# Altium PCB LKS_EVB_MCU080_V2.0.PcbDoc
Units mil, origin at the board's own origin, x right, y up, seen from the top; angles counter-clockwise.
Board outline 2625 x 1560 mil, 2 copper layers (Top Layer, Bottom Layer); 45 components, 81 nets, 209 pads, 59 vias.
Unrouted connection lines stored in the file: 4.
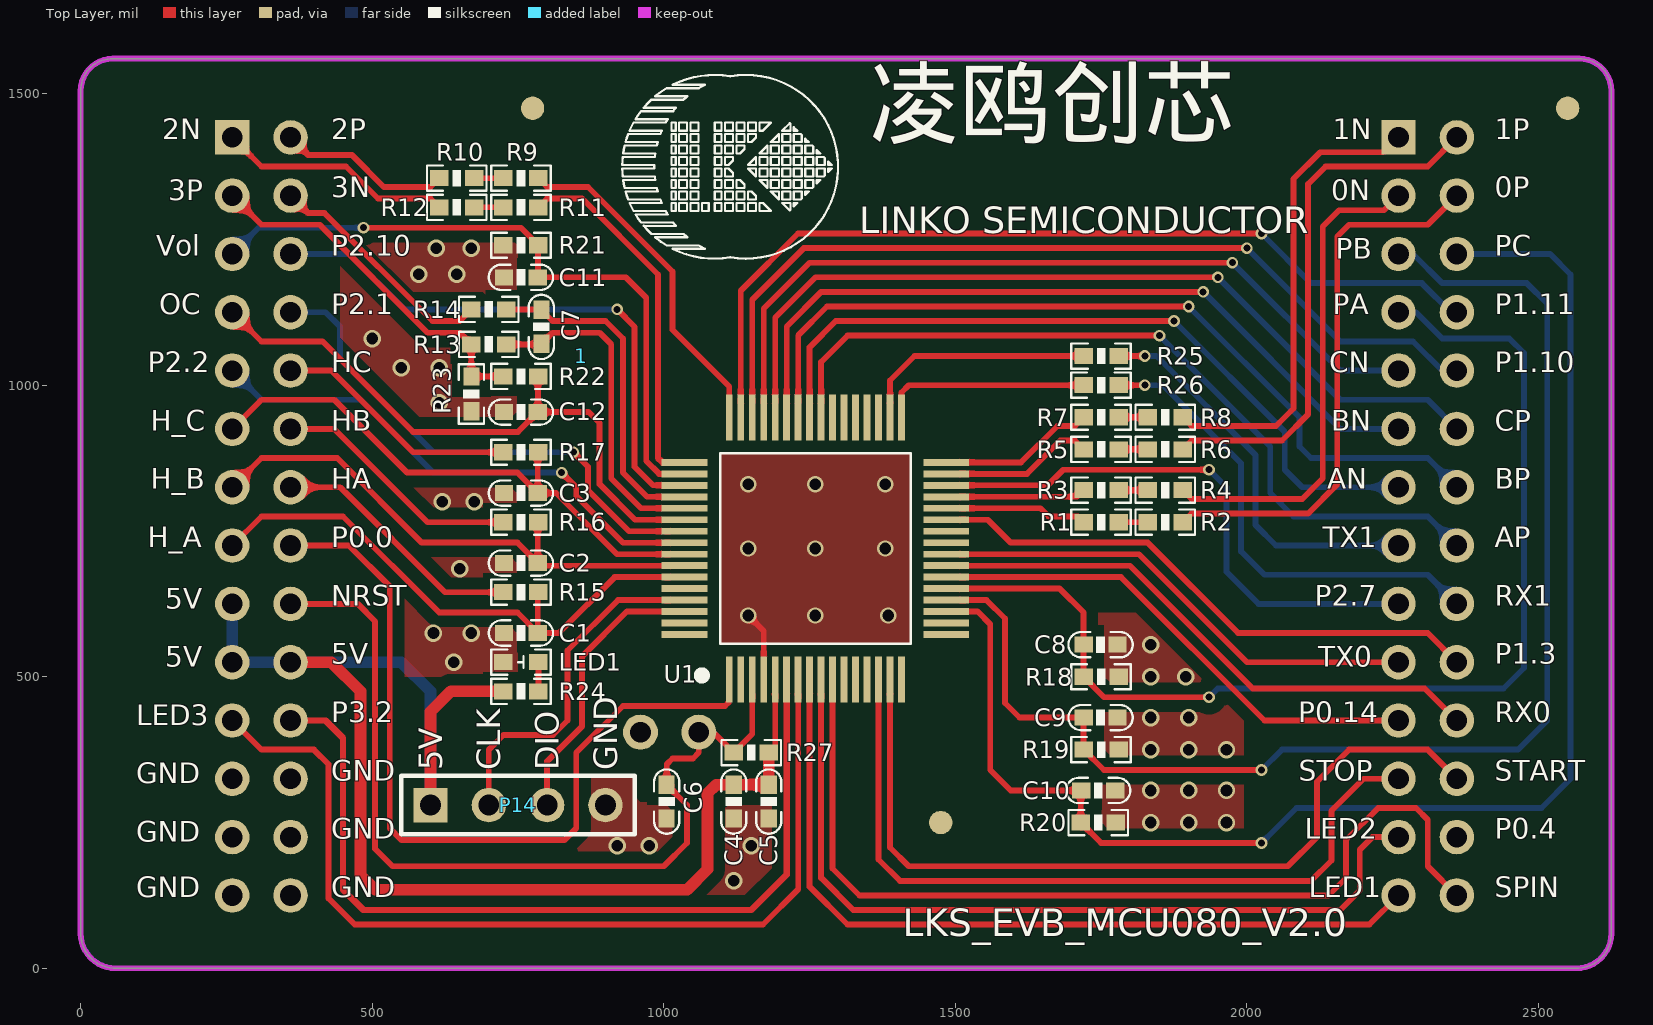
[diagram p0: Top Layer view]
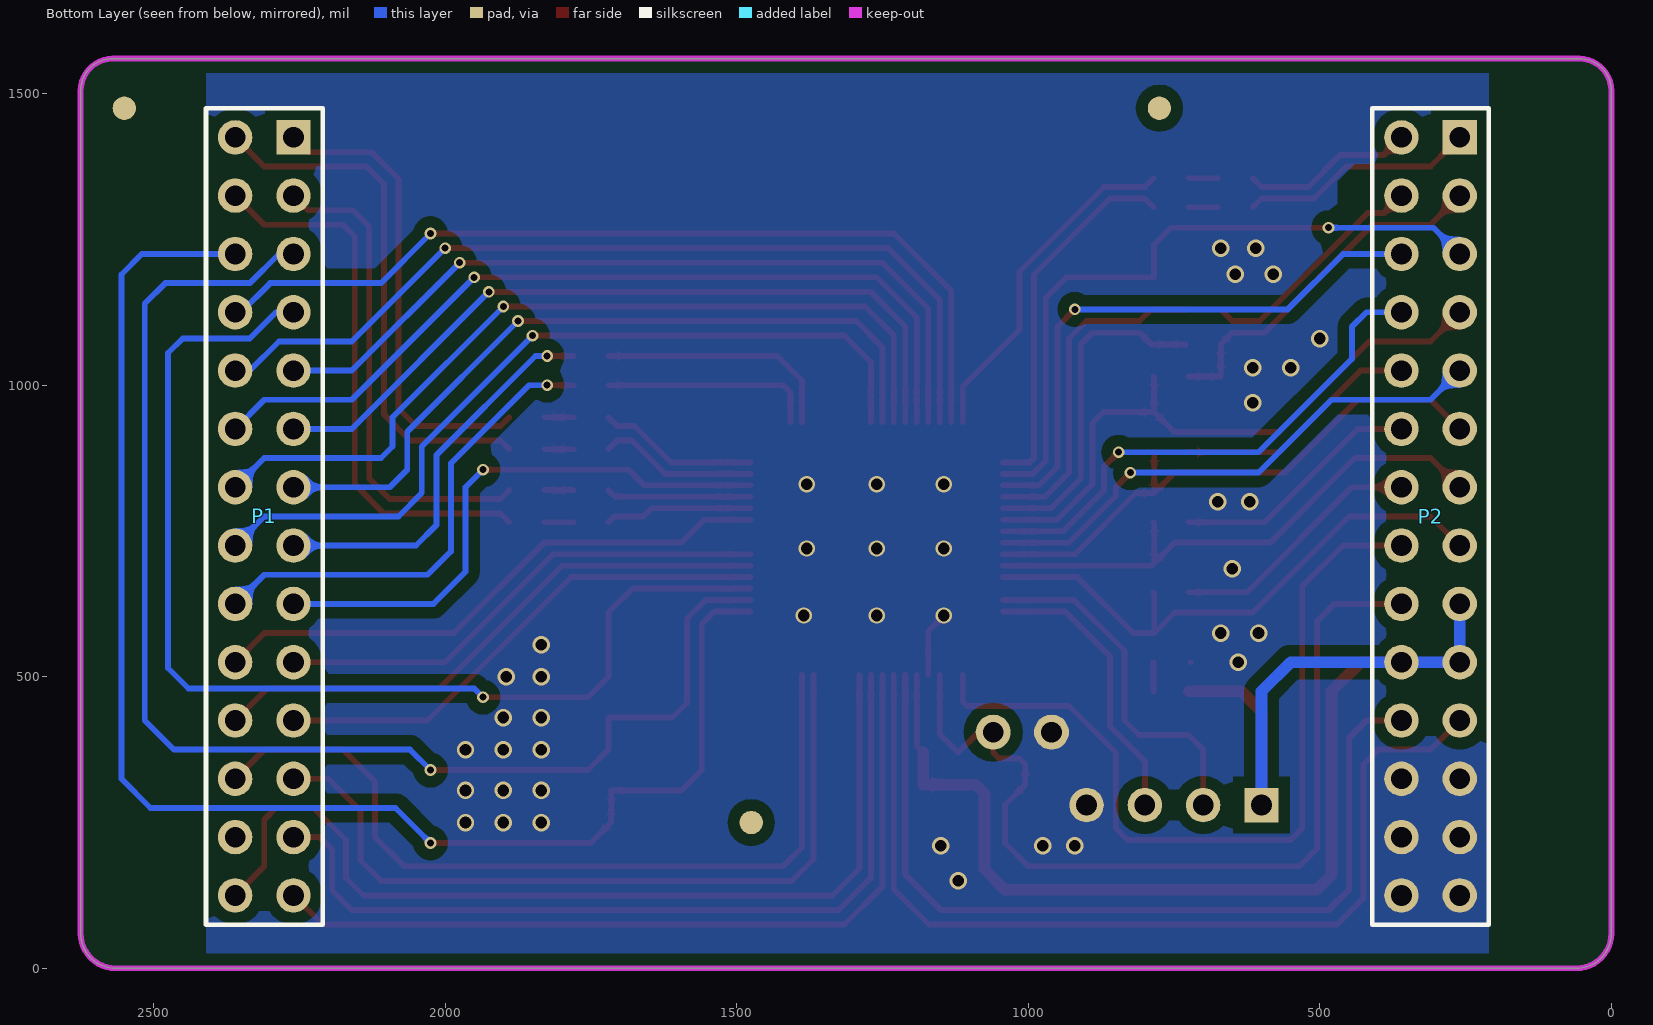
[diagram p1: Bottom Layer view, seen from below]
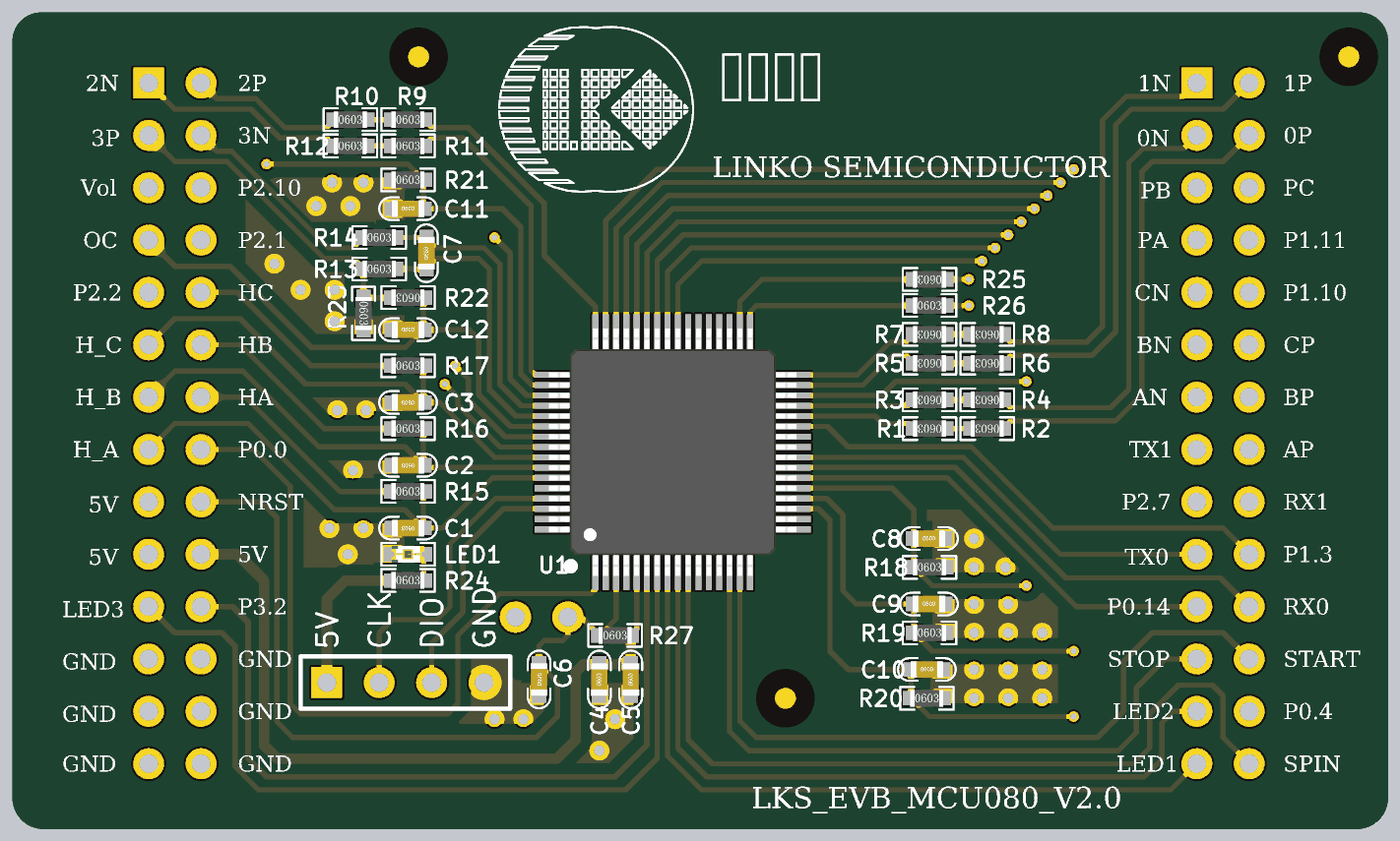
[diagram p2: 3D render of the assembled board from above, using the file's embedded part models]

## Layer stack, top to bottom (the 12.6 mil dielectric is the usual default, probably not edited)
Top Solder: solder mask 0.4, Solder Resist, Dk 3.5
Top Layer: signal copper 1.4
Dielectric1: dielectric 12.6, FR-4, Dk 4.8
Bottom Layer: signal copper 1.4
Bottom Solder: solder mask 0.4, Solder Resist, Dk 3.5

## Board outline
0,60 0,1505 cw(c55,1505) 55,1560 2570,1560 cw(c2570,1505) 2625,1505 2625,60 cw(c2565,60) 2565,0 60,0 cw(c60,60)

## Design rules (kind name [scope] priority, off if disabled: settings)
Clearance Clearance_2 [InPolygon] p1: gap=20 ignorepadtopadclearanceinfootprint=FALSE except(0: Arc-Hole Track-Hole SMDPad-Hole THPad-Hole Via-Hole Fill-Hole Poly-Hole Region-Hole Text-Hole)
Clearance Clearance_1 [All] p2: gap=0 ignorepadtopadclearanceinfootprint=FALSE
ComponentClearance [All] p1: gap=0 collisioncheckmode=3 verticalgap=0 showdistances=FALSE
FabricationTestpoint [(IsPad And (OnTopLayer Or OnBottomLayer))] p1: side=3 testpointundercomponent=TRUE minsize=40 maxsize=100 preferedsize=60 minholesize=0 maxholesize=40 preferedholesize=32 testpointgrid=1 allowsidetop=TRUE allowsidebottom=TRUE usegrid=TRUE gridtolerance=0.01
HoleSize [All] p1: absolutevalues=TRUE maxlimit=100 minlimit=0 maxpercent=80.000 minpercent=20.000
PolygonConnect [All] p1: connectstyle=Direct reliefconductorwidth=10 reliefentries=4 polygonreliefangle="90 Angle" airgapwidth=10
RoutingVias [All] p1: holewidth=28 width=50 viastyle="Through Hole" minholewidth=0 minwidth=10 maxholewidth=28 maxwidth=50
SilkToSolderMaskClearance SilkscreenOverComponentPads [IsPad] p1: minsilkscreentomaskgap=10 clearancetoexposedcopper=TRUE
SolderMaskExpansion [All] p1: expansion=4 istentingtop=FALSE
Width [All] p1: maxlimit=100 minlimit=1 preferedwidth=10
26 further rules are at their usual default settings.

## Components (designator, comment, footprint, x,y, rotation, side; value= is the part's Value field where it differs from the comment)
1 "LKS_sign" LKS_LOGO2 858.51,1050 r0 top
C1 "10nF/16V" 0603C 755,575 r180 top
C2 "10nF/16V" 0603C 755,695 r180 top
C3 "10nF/16V" 0603C 755,815 r180 top
C4 "10uF/10V" 0603C 1120,285.95 r90 top
C5 "100nF/50V" 0603C 1180,285.95 r90 top
C6 "100nF/50V" 0603C 1005,286 r270 top
C7 "1nF/50V" 0603C 790,1100 r90 top
C8 "1nF/50V" 0603C 1749,555 r0 top
C9 "1nF/50V" 0603C 1749,430 r0 top
C10 "1nF/50V" 0603C 1745,305 r0 top
C11 "100nF/50V" 0603C 755,1185 r0 top
C12 "1nF/50V" 0603C 755,953.86 r0 top
LED1 "LED" "LED 0603R" 755,525 r180 top
P1 "Header 14X2A" HDR2X14_CEN 2260,1425 r270 bottom
P2 "Header 14X2A" HDR2X14_CEN 260,1425 r270 bottom
P14 "Header 4" HDR1X4 600,280 r0 top
R1 "20K1%" 0603R 1750,765 r180 top value=K
R2 "20K1%" 0603R 1860,765 r180 top value=K
R3 "20K1%" 0603R 1750,820 r180 top value=K
R4 "20K1%" 0603R 1860,820 r180 top value=K
R5 "20K1%" 0603R 1750,890 r180 top value=K
R6 "20K1%" 0603R 1860,890 r180 top value=K
R7 "20K1%" 0603R 1750,945 r180 top value=K
R8 "20K1%" 0603R 1860,945 r180 top value=K
R9 "20K1%" 0603R 755,1355 r0 top value=K
R10 "20K1%" 0603R 645,1355 r0 top value=K
R11 "20K1%" 0603R 755,1305 r0 top value=K
R12 "20K1%" 0603R 645,1305 r0 top value=K
R13 "1K1%" 0603R 700,1070 r0 top value=K
R14 "1K1%" 0603R 700,1130 r0 top value=K
R15 "2K" 0603R 755,645 r0 top value=K
R16 "2K" 0603R 755,765 r0 top value=K
R17 "2K" 0603R 755,885 r0 top value=K
R18 "1K" 0603R 1750,500 r0 top value=K
R19 "1K" 0603R 1750,375 r0 top value=K
R20 "1K" 0603R 1745,250 r0 top value=K
R21 "1K1%" 0603R 755,1240 r0 top value=K
R22 "1K1%" 0603R 755,1015 r180 top value=K
R23 "10R" 0603R 670,985 r270 top value=K
R24 "330R" 0603R 755,475 r0 top value=K
R25 "10R" 0603R 1750,1050 r180 top value=K
R26 "10R" 0603R 1750,1000 r0 top value=K
R27 "20K1%" 0603R 1150,370 r0 top value=K
U1 "LKS080" LQFP64 1260,720 r0 top locked

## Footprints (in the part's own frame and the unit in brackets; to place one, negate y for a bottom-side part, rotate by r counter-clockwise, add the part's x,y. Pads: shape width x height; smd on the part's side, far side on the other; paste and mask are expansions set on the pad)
0603C [mm] "电容"
  rect 0.8x0.7 smd: 1(-0.737,0) 2(0.738,0)
  silkscreen extent -1.4,-0.55 1.4,0.55, body extent -0.8,-0.41 0.8,0.41, height 0.81
0603R [mm] "电阻"
  rect 0.8x0.7 smd: 1(-0.762,0) 2(0.762,0)
  silkscreen extent -1.3,-0.55 1.3,0.55, body extent -0.8,-0.4 0.8,0.4, height 0.45
HDR1X4 [mm] "Connector; Header; 4 Position"
  rect 1.5x1.5 hole 0.9: 1(0,0)
  round 1.5 hole 0.9: 2(2.54,0) 3(5.08,0) 4(7.62,0)
  silkscreen extent -1.27,-1.27 8.89,1.27
HDR2X14_CEN [mm] "Connector; Header; 14x2 Position"
  rect 1.5x1.5 hole 0.9: 1(0,0)
  round 1.5 hole 0.9: 2(2.54,0) 3(5.08,0) 4(7.62,0) 5(10.16,0) 6(12.7,0) 7(15.24,0) 8(17.78,0) 9(20.32,0) 10(22.86,0) 11(25.4,0) 12(27.94,0) 13(30.48,0) 14(33.02,0) 15(0,-2.54) 16(2.54,-2.54) 17(5.08,-2.54) 18(7.62,-2.54) 19(10.16,-2.54) 20(12.7,-2.54) 21(15.24,-2.54) 22(17.78,-2.54) 23(20.32,-2.54) 24(22.86,-2.54) 25(25.4,-2.54) 26(27.94,-2.54) 27(30.48,-2.54) 28(33.02,-2.54)
  silkscreen extent -1.27,-3.81 34.29,1.27
"LED 0603R" [mm] "LED"
  rect 0.8x0.7 smd: 1(-0.762,0) 2(0.762,0)
  silkscreen extent -1.3,-0.55 1.3,0.55, body extent -0.8,-0.4 0.8,0.4, height 0.47
LKS_LOGO2 [mil] "标?"
  silkscreen extent 70,167 440,482
LQFP64 [mm] "LINKO-080"
  rect 0.3x2 smd: 1(-3.75,-5.7) 2(-3.25,-5.7) 3(-2.75,-5.7) 4(-2.25,-5.7) 5(-1.75,-5.7) 6(-1.25,-5.7) 7(-0.75,-5.7) 8(-0.25,-5.7) 9(0.25,-5.7) 10(0.75,-5.7) 11(1.25,-5.7) 12(1.75,-5.7) 13(2.25,-5.7) 14(2.75,-5.7) 15(3.25,-5.7) 16(3.75,-5.7) 33(3.75,5.7) 34(3.25,5.7) 35(2.75,5.7) 36(2.25,5.7) 37(1.75,5.7) 38(1.25,5.7) 39(0.75,5.7) 40(0.25,5.7) 41(-0.25,5.7) 42(-0.75,5.7) 43(-1.25,5.7) 44(-1.75,5.7) 45(-2.25,5.7) 46(-2.75,5.7) 47(-3.25,5.7) 48(-3.75,5.7)
  rect 2x0.3 smd: 17(5.7,-3.75) 18(5.7,-3.25) 19(5.7,-2.75) 20(5.7,-2.25) 21(5.7,-1.75) 22(5.7,-1.25) 23(5.7,-0.75) 24(5.7,-0.25) 25(5.7,0.25) 26(5.7,0.75) 27(5.7,1.25) 28(5.7,1.75) 29(5.7,2.25) 30(5.7,2.75) 31(5.7,3.25) 32(5.7,3.75) 49(-5.7,3.75) 50(-5.7,3.25) 51(-5.7,2.75) 52(-5.7,2.25) 53(-5.7,1.75) 54(-5.7,1.25) 55(-5.7,0.75) 56(-5.7,0.25) 57(-5.7,-0.25) 58(-5.7,-0.75) 59(-5.7,-1.25) 60(-5.7,-1.75) 61(-5.7,-2.25) 62(-5.7,-2.75) 63(-5.7,-3.25) 64(-5.7,-3.75)
  silkscreen extent -5.12,-5.71 4.15,4.15, body extent -6,-6 6,6, height 1.05

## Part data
C1 C2 C3 C8 C9 C10: library part CAP, "Capacitor"
C4 C5 C6 C7 C11 C12: library part C, "Capacitor"
LED1: "LED_Light"
P1 P2: "Header, 14-Pin, Dual row"
P14: "Header, 4-Pin"
R1 R2 R3 R4 R5 R6 R7 R8 R9 R10 R11 R12 R13 R14 R15 R16 R17 R18 R19 R20 R21 R22 R23 R24 R25 R26 R27: library part Res, "Resistor"

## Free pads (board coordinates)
  round 60 hole 35.43: 0(960,405) 1(1060,405)
  round 40 all layers, no hole: 0(2550,1475) 1(775,1475) 2(1475,250)

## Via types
v1: diameter 30, hole 20, Top Layer to Bottom Layer, 32 vias
v2: diameter 20, hole 12, Top Layer to Bottom Layer, 18 vias
v3: diameter 28, hole 20, Top Layer to Bottom Layer, 9 vias

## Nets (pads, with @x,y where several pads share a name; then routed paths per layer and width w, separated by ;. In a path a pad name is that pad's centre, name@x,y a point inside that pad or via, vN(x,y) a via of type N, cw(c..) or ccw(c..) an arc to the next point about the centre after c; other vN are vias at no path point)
+5V: C4.2 C5.2 P2.9 P2.10 P2.24 P14.1 R24.1 R27.2 U1.5 | length 2465
  Top Layer w10: R27.2 1191.1,381.1 U1.5@1191.1,503.46
  Top Layer w20: P2.24 430,525 480,475 480,160 505,135 1040,135 1075,170 1075,300 1090,315 C4.2 C5.2 R27.2 ; P14.1 600,440 635,475 R24.1
  Bottom Layer w20: P2.9 P2.10 P2.24 550,525 600,475 P14.1
CAN_RX: U1.11
CAN_TX: U1.12
GND: C1.2 C2.2 C3.2 C4.1 C5.1 C6.2 C8.2 C9.2 C10.2 C11.1 C12.1 LED1.2 P2.12 P2.13 P2.14 P2.16 P2.26 P2.27 P2.28 P14.4 pad.0@960,405 R14.1 R18.2 R19.2 R20.2 R21.1 R23.2 U1.4 | length 522.8
  Top Layer w7.87: LED1.2@720,525 LED1.2@723,525
  Top Layer w10: P2.16 390,1295 418.28,1295 603.28,1110 650,1110 R14.1 ; v3(1145,605) 1171.42,578.58 U1.4@1171.42,503.46
  other v1: 1120,150 920,210 975,210 1150,210 1835,250 1900,250 1965,250 1835,305 1900,305 1965,305 1835,375 1900,375 1965,375 1835,430 1900,430 1835,500 1895,500 640,525 1835,555 605,575 670,575 650,685 620,800 675,800 615,970 550,1030 615,1030 500,1080 580,1190 645,1190 610,1235 670,1235
  other v3: 1260,605 1385,605 1145,720 1260,720 1380,720 1145,830 1260,830 1380,830
HALL_U: C1.1 P2.8 R15.2 U1.59 | length 997.1
  Top Layer w10: P2.8 310,775 450,775 615,610 749,610 C1.1 ; R15.2 784,644 C1.1 ; U1.59@1043.46,670.79 915.79,670.79 820,575 C1.1
HALL_V: C2.1 P2.7 R16.2 U1.58 | length 951
  Top Layer w10: P2.7 310,875 440,875 585,730 749,730 C2.1 ; R16.2 784,764 C2.1 ; U1.58@1043.46,690.47 788.53,690.47 C2.1
HALL_W: C3.1 P2.6 R17.2 U1.57 | length 984.3
  Top Layer w10: P2.6 310,975 435,975 560,850 749,850 C3.1 ; R17.2 784,884 C3.1 ; U1.57@1043.46,710.16 919.84,710.16 815,815 C3.1
HU: P2.21 R15.1 | length 439.6
  Top Layer w10: P2.21 445,825 625,645 R15.1
HV: P2.20 R16.1 | length 431.3
  Top Layer w10: P2.20 435,925 595,765 R16.1
HW: P2.19 R17.1 | length 423
  Top Layer w10: P2.19 430,1025 570,885 R17.1
LED1: P1.14 U1.8 | length 1421
  Top Layer w10: U1.8@1250.16,503.46 1250.16,139.84 1315,75 2210,75 P1.14
LED2: P1.13 U1.9 | length 1454.1
  Top Layer w10: U1.9@1269.84,503.46 1269.84,155.16 1325,100 2160,100 2193.56,133.56 2193.56,203.56 2215,225 P1.13
LED3: P2.11 U1.7 | length 1643.2
  Top Layer w10: P2.11 310,375 400,375 425,350 425,120 470,75 1170,75 1230.47,135.47 U1.7@1230.47,503.46
NetLED1_1: LED1.1 R24.2 | length 50
  Top Layer w10: R24.2 LED1.1
NetR1_1: R1.1 R2.2 | length 50
  Top Layer w10: R1.1 R2.2
NetR3_1: R3.1 R4.2 | length 50
  Top Layer w10: R3.1 R4.2
NetR5_1: R5.1 R6.2 | length 50
  Top Layer w10: R5.1 R6.2
NetR7_1: R7.1 R8.2 | length 50
  Top Layer w10: R7.1 R8.2
NetR9_1: R9.1 R10.2 | length 50
  Top Layer w10: R10.2 R9.1
NetR11_1: R11.1 R12.2 | length 50
  Top Layer w10: R12.2 R11.1
NetR25_2: R25.2 U1.34 | length 420.9
  Top Layer w10: U1.34@1387.95,936.54 1387.95,1007.95 1430,1050 R25.2
NetR26_1: R26.1 U1.33 | length 368.6
  Top Layer w10: U1.33@1407.64,936.54 1407.64,987.64 1420,1000 R26.1
NRST: C6.1 P2.23 pad.1@1060,405 R27.1 U1.3 | length 1580.3
  Top Layer w10: P2.23 475,625 505,595 505,205 535,175 1000,175 1040,215 1040,280 C6.1 1005,350 1015,360 1050,360 1060,370 1060,405 1085,405 R27.1 1151.73,401.73 U1.3@1151.73,503.46
OC: C12.2 P2.4 R22.1 U1.54 | length 1081.9
  Top Layer w10: P2.4 310,1075 415,1075 570,920 750.2,920 C12.2 ; R22.1 784.05,1014.05 C12.2 ; U1.54@1043.46,769.21 950.79,769.21 890,830 890,935 871.14,953.86 C12.2
OPA0_IN: R3.2 U1.29 | length 248.2
  Top Layer w10: U1.29@1476.54,808.58 1708.58,808.58 R3.2
OPA0_IP: R1.2 U1.28 | length 253.4
  Top Layer w10: U1.28@1476.54,788.9 1646.1,788.9 1660,775 1710,775 R1.2
OPA1_IN: R7.2 U1.32 | length 275.5
  Top Layer w10: U1.32@1476.54,867.64 1612.64,867.64 1675,930 1705,930 R7.2
OPA1_IP: R5.2 U1.31 | length 273.3
  Top Layer w10: U1.31@1476.54,847.95 1622.95,847.95 1680,905 1705,905 R5.2
OPA2_IN: R11.2 U1.49 | length 636.6
  Top Layer w10: R11.2 800,1320 860,1320 990,1190 990,875 997.36,867.64 U1.49@1043.46,867.64
OPA2_IP: R9.2 U1.48 | length 595.1
  Top Layer w10: R9.2 800,1340 870,1340 1015,1195 1015,1095 1112.36,997.64 U1.48@1112.36,936.54
OPA3_IN: C7.2 R14.2 U1.52 | length 581.3
  Top Layer w10: R14.2 789.05,1130 C7.2 809.05,1110 900,1110 930,1080 930,850 971.42,808.58 U1.52@1043.46,808.58
OPA3_IP: C7.1 R13.2 U1.53 | length 581.2
  Top Layer w10: R13.2 789,1070 C7.1 809,1090 890,1090 910,1070 910,840 961.1,788.9 U1.53@1043.46,788.9
P0.0: P2.22 U1.1 | length 1425.2
  Top Layer w10: P2.22 460,725 530,655 530,240 550,220 830,220 850,240 850,370 930,450 1105,450 1112.36,457.36 U1.1@1112.36,503.46
P0.1: U1.2
P0.4: P1.27
P0.8: U1.16
P0.9: U1.17
P0.10: U1.18
P0.14: P1.11 U1.22 | length 885.3
  Top Layer w10: U1.22@1476.54,670.79 1784.21,670.79 2030,425 P1.11
P1.1: U1.13
P1.2: U1.26
P1.3: P1.24 U1.27 | length 984.6
  Top Layer w10: U1.27@1476.54,769.21 1555.79,769.21 1595,730 1830,730 1985,575 2310,575 P1.24
P1.10: P1.19 U1.46 | length 1542
  Top Layer w10: U1.46@1151.73,936.54 1151.73,1146.73 1240,1235 v2(2000,1235)
  Bottom Layer w10: v2(2000,1235) 2160,1075 2285,1075 2335,1025 P1.19
P1.11: P1.18 U1.47 | length 1550
  Top Layer w10: U1.47@1132.05,936.54 1132.05,1162.05 1230,1260 v2(2025,1260)
  Bottom Layer w10: v2(2025,1260) 2110,1175 2300,1175 2350,1125 P1.18
P1.12: U1.35
P1.13: U1.36
P1.14: U1.37
P1.15: U1.38
P2.0: U1.39
P2.1: P2.18 U1.55 | length 894.6
  Top Layer w10: v2(845,885) 870,860 870,820 940.47,749.53 U1.55@1043.46,749.53
  Bottom Layer w10: P2.18 420,1125 445,1100 445,1045 605,885 v2(845,885)
P2.2: P2.5 U1.56 | length 914.5
  Top Layer w10: v2(825,850) 850,825 850,810 930.16,729.84 U1.56@1043.46,729.84
  Bottom Layer w10: P2.5 310,975 480,975 605,850 v2(825,850)
P2.7: P1.9 U1.30 | length 974.7
  Top Layer w10: U1.30@1476.54,828.27 1658.27,828.27 1685,855 v2(1935,855)
  Bottom Layer w10: v2(1935,855) 1965,825 1965,680 2020,625 P1.9
P2.10: P2.17 U1.51 | length 988.4
  Top Layer w10: v2(920,1130) 950,1100 950,860 981.73,828.27 U1.51@1043.46,828.27
  Bottom Layer w10: P2.17 460,1225 555,1130 v2(920,1130)
P2.13: U1.60
P2.14: U1.63
P2.15: U1.64
P3.2: P2.25 U1.6 | length 1505.6
  Top Layer w11: P2.25 420,425 450,395 450,135 485,100 1150,100 1210.79,160.79 U1.6@1210.79,503.46
P3.6: U1.25
PGND: P1.1 P1.2 P2.1 P2.2 R4.1 R8.1 R12.1 R13.1 R22.2 R23.1 | length 2687.1
  Top Layer w10: P2.2 310,1275 410,1275 595,1090 650,1090 R13.1 R23.1 R22.2 ; P2.1 310,1375 455,1375 510,1320 600,1320 R12.1 ; R4.1 1905,805 2095,805 2130,840 2130,1272.27 2157.73,1300 2235,1300 P1.2 ; R8.1 1905,930 2050,930 2080,960 2080,1353.77 2125.64,1399.41 2234.41,1399.41 P1.1
PU: C8.1 P1.4 R18.1 U1.21 | length 1944.7
  Top Layer w10: U1.21@1476.54,651.1 1678.9,651.1 1720,610 C8.1 R18.1 1755,465 v2(1935,465)
  Bottom Layer w10: v2(1935,465) 1950,480 2440,480 2475,515 2475,1055 2450,1080 2335,1080 2290,1125 P1.4
PV: C9.1 P1.3 R19.1 U1.20 | length 2316.7
  Top Layer w10: U1.20@1476.54,631.42 1553.58,631.42 1585,600 1585,455 1610,430 C9.1 R19.1 1755,340 v2(2025,340)
  Bottom Layer w10: v2(2025,340) 2060,375 2465,375 2515,425 2515,1140 2480,1175 2335,1175 2285,1225 P1.3
PW: C10.1 P1.17 R20.1 U1.19 | length 2542.9
  Top Layer w10: U1.19@1476.54,611.73 1538.27,611.73 1560,590 1560,340 1595,305 C10.1 1715,304 R20.1 1750,215 v2(2025,215)
  Bottom Layer w10: v2(2025,215) 2085,275 2505,275 2555,325 2555,1190 2520,1225 P1.17
RXD0: P1.25 U1.23 | length 993.4
  Top Layer w10: U1.23@1476.54,690.47 1799.53,690.47 2010,480 2305,480 P1.25
RXD1: P1.23 R26.2 | length 823.8
  Top Layer w10: R26.2 v2(1825,1000)
  Bottom Layer w10: v2(1825,1000) 1856,1000 1990,866 1990,715 2030,675 2310,675 P1.23
SPIN: P1.28 U1.10 | length 1631.1
  Top Layer w10: U1.10@1289.53,503.46 1289.53,171.22 1335.75,125 2140,125 2170,155 2170,220 2225,275 2290,275 2310,255 2310,175 P1.28
START1: P1.26 U1.15 | length 1440.9
  Top Layer w10: U1.15@1387.95,503.46 1387.95,207.05 1420,175 2070,175 2120,225 2120,320 2175,375 2310,375 P1.26
STOP1: P1.12 U1.14 | length 1346
  Top Layer w10: U1.14@1368.27,503.46 1368.27,186.73 1405,150 2110,150 2145,185 2145,270 2200,325 P1.12
SWCLK: P14.2 U1.61 | length 615
  Top Layer w10: P14.2 700,375 725,400 810,400 835,425 835,545 921.42,631.42 U1.61@1043.46,631.42
SWDIO: P14.3 U1.62 | length 495.1
  Top Layer w10: P14.3 800,355 860,415 860,535 936.73,611.73 U1.62@1043.46,611.73
TXD0: P1.10 U1.24 | length 860.2
  Top Layer w10: U1.24@1476.54,710.16 1814.84,710.16 2000,525 P1.10
TXD1: P1.8 R25.1 | length 684.9
  Top Layer w10: R25.1 v2(1825,1050)
  Bottom Layer w10: v2(1825,1050) 1845,1050 2015,880 2015,760 2050,725 P1.8
UN: P1.7 U1.41 | length 1313.2
  Top Layer w10: U1.41@1250.16,936.54 1250.16,1065.16 1295,1110 v2(1875,1110)
  Bottom Layer w10: v2(1875,1110) 2065,920 2065,855 2095,825 P1.7
UP: P1.22 U1.40 | length 1408.1
  Top Layer w10: U1.40@1269.84,936.54 1269.84,1039.84 1315,1085 v2(1850,1085)
  Bottom Layer w10: v2(1850,1085) 2040,895 2040,815 2080,775 2310,775 P1.22
UP-: P2.15 R10.1 | length 296.4
  Top Layer w10: P2.15 390,1395 465,1395 520,1340 600,1340 R10.1
VN: P1.6 U1.43 | length 1335.3
  Top Layer w10: U1.43@1210.79,936.54 1210.79,1100.79 1270,1160 v2(1925,1160)
  Bottom Layer w10: v2(1925,1160) 2160,925 P1.6
VOL_ADC: C11.2 P2.3 R21.2 U1.50 | length 1174.5
  Top Layer w10: v2(485,1270) 755,1270 R21.2 784.05,1239.06 C11.2 935,1185 970,1150 970,870 992.05,847.95 U1.50@1043.46,847.95
  Bottom Layer w10: P2.3 305,1270 v2(485,1270)
VP: P1.21 U1.42 | length 1456.7
  Top Layer w10: U1.42@1230.47,936.54 1230.47,1085.47 1280,1135 v2(1900,1135)
  Bottom Layer w10: v2(1900,1135) 2090,945 2090,895 2110,875 2310,875 P1.21
VP-: P1.15 R6.1 | length 923
  Top Layer w10: R6.1 1905,905 2060,905 2105,950 2105,1345 2135,1375 2310,1375 P1.15
WN: P1.5 U1.45 | length 1392.6
  Top Layer w10: U1.45@1171.42,936.54 1171.42,1131.42 1250,1210 v2(1975,1210)
  Bottom Layer w10: v2(1975,1210) 2160,1025 P1.5
WP: P1.20 U1.44 | length 1484.7
  Top Layer w10: U1.44@1191.1,936.54 1191.1,1116.1 1260,1185 v2(1950,1185)
  Bottom Layer w10: v2(1950,1185) 2160,975 2310,975 P1.20
WP-: P1.16 R2.1 | length 950.9
  Top Layer w10: R2.1 1905,780 2105,780 2155,830 2155,1255 2175,1275 2310,1275 P1.16

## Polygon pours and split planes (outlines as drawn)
GND on Top Layer "NONET_L-01_P-001" (solid, remove dead copper, pour order 16): 749.68,500 755,505.32 755,1270 475,1270 440,1235 445,1230 445,550 495,500
GND on Top Layer "NONET_L-01_P-001" (solid, remove dead copper, pour order 15): 850,330 850,175 1015,175 1090,100 1150,100 1210.79,160.79 1210,161.58 1210,285 960,285 950,295 950,330
GND on Top Layer "NONET_L-01_P-001" (solid, remove dead copper, pour order 13): 1720,610 1845,610 1994.74,460.26 1994.74,215 1750,215 1715,250
GND on Top Layer "NONET_L-01_P-001" (solid, remove dead copper, pour order 14): 1096.61,883.39 1423.39,883.39 1423.39,556.61 1096.61,556.61
GND on Bottom Layer "Bottom Layer-No Net 1" (solid, remove dead copper, pour order 12): 210,1560 210,0 2410,0 2410,1560

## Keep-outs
Keep-Out Layer:
  the board outline again, w10

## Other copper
Top Layer:
  pour cut-out: 225.01,1380.02 230.03,1375 485,1375 485,1245 570,1160 690,1160 700,1150 700,1085.76 694.25,1080 590,1080 395,1275 225,1275
Bottom Layer:
  pour cut-out: 225.01,1380.02 440.01,1380.02 470.01,1350.02 470.01,1260.02 454.99,1245 225.01,1245

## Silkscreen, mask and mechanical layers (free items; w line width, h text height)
Top Overlay:
  text "2N" at 140,1410 h60
  text "2P" at 430,1410 h60
  text "1N" at 2147.11,1410 h60
  text "1P" at 2425,1410 h60
  text "3N" at 429.94,1310 h60
  text "0P" at 2425,1310 h60
  text "3P" at 150,1305 h60
  text "0N" at 2145,1305 h60
  text "Vol" at 130,1210 h60
  text "P2.10" at 430,1210 h60
  text "PC" at 2425,1210 h60
  text "PB" at 2152.1,1205 h60
  text "OC" at 135,1110 h60
  text "P2.1" at 430,1110 h60
  text "PA" at 2146.83,1110 h60
  text "P1.11" at 2425,1110 h60
  text "P2.2" at 115,1010 h60
  text "HC" at 430,1010 h60
  text "CN" at 2140.89,1010 h60
  text "P1.10" at 2425,1010 h60
  text "H_C" at 120,910 h60
  text "HB" at 430,910 h60
  text "BN" at 2145,910 h60
  text "CP" at 2425,910 h60
  text "H_B" at 120,810 h60
  text "HA" at 430,810 h60
  text "AN" at 2137.56,810 h60
  text "BP" at 2425,810 h60
  text "H_A" at 115,710 h60
  text "P0.0" at 430,710 h60
  text "TX1" at 2130.18,710 h60
  text "AP" at 2425,710 h60
  text "NRST" at 430,610 h60
  text "P2.7" at 2116.36,610 h60
  text "RX1" at 2425,610 h60
  text "5V" at 145,605 h60
  text "5V" at 429.94,510 h60
  text "P1.3" at 2425,510 h60
  text "5V" at 145,505 h60
  text "TX0" at 2122.47,505 h60
  text "P3.2" at 430,410 h60
  text "P0.14" at 2088.22,410 h60
  text "RX0" at 2425,410 h60
  text "LED3" at 95,405 h60
  text "5V" at 620,340 h40 r90
  text "CLK" at 720,340 h40 r90
  text "DIO" at 820,340 h40 r90
  text "GND" at 920,340 h40 r90
  text "GND" at 430,310 h60
  text "STOP" at 2089.22,310 h60
  text "START" at 2425,310 h60
  text "GND" at 95,305 h60
  text "GND" at 430,210 h60
  text "LED2" at 2098.88,210 h60
  text "P0.4" at 2425,210 h60
  text "GND" at 95,205 h60
  text "GND" at 95,110 h60
  text "GND" at 430,110 h60
  text "LED1" at 2106.15,110 h60
  text "SPIN" at 2425,110 h60
  text "LKS_EVB_MCU080_V2.0" at 1410,40 h80
Top Solder:
  circle w78: c2550,1475 r17
  circle w78: c775,1475 r17
  circle w78: c1475,250 r17
Mechanical 1:
  the board outline again, w10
